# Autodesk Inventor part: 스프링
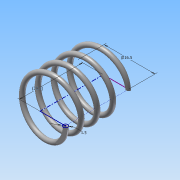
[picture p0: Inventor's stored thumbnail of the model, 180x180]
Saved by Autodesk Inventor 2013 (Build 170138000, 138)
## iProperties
Created: 2015-08
Part Number: 스프링
Material: 강철, 연강
Document SubType Name: Modeling
Designer: Administrator
Mass: 2.84502 g
Surface Area: 9.78731 cm^2
Volume: 0.361961 cm^3
Density: 7.86 g/cm^3
Author: Administrator
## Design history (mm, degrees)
sketch "스케치1"
  geometry: L1 (0, 0)-(8.25, 0); L2 (8.25, 0)-(8.25, 28); L3 (8.25, 28)-(0, 28); L4 (0, 28)-(0, 0); C1 r 0.75 at (8.25, 0)
  constraints: 8 end point, 2 parallel, 1 centre point, 1 coincident, 1 horizontal, 1 perpendicular
  dimensions: "d0" = 28 distance between parallel lines of L1 L3 (derived); "d2" = 16.5 diameter of L2 L4; "d3" = 1.5 diameter of C1
feature "코일1" sketch "스케치1" pitch "d4" = 10; turns "d6" = 4; dims "d5" = 28 (= d0), "d7" = 0, angle "d8" = 90 deg, angle "d9" = 90 deg, "d10" = 0, "d11" = 0
feature "분할1"
node "작업 평면1"
feature "분할2"
node "솔리드1"
other parameters: "d12" = 90 deg
